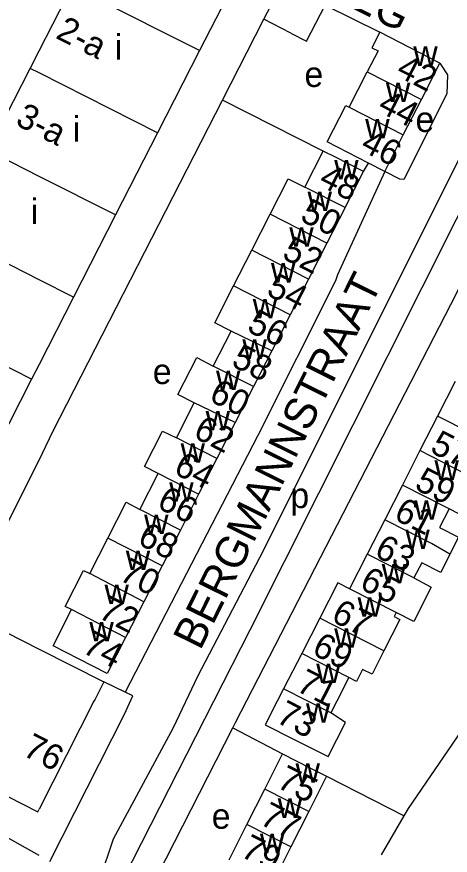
# Model space of a CAD drawing. Extents: x 159700 to 161346, y 381730 to 382922.
# Drawn here: x 160696.5 to 160765.1, y 382225.6 to 382358.4 of the extents above; entities that cross this region are included whole.
import ezdxf

# ---------------------------------------------------------------- set-up
doc = ezdxf.new("R2010")
doc.units = 0
for name, color, linetype in [('BLT_Basislijn', 7, 'Continuous'), ('BLT_Bebouwing', 7, 'Continuous'), ('BLT_Centroide', 7, 'Continuous'), ('BLT_Huisnummer', 7, 'Continuous'), ('BLT_Huisnummer_ tussenligend', 7, 'Continuous'), ('BLT_Huisnummer_reeks', 7, 'Continuous'), ('BLT_Onderverdeling_panden', 7, 'Continuous'), ('BLT_Straatnaam', 7, 'Continuous')]:
    doc.layers.add(name, color=color, linetype=linetype)

msp = doc.modelspace()

# ---------------------------------------------------------------- linework, layer by layer
at = {"layer": 'BLT_Basislijn'}
for p, q in [((160745.3, 382360.23), (160753.96, 382355.93)), ((160729.04, 382345.2), (160735.6, 382358)), ((160745.01, 382337.11), (160729.04, 382345.2)), ((160751.38, 382333.88), (160752.15, 382335.23)), ((160713.63, 382251.43), (160710.25, 382253.07)), ((160715.82, 382216.7), (160730.71, 382245.8)), ((160730.71, 382245.8), (160738.54, 382241.65)), ((160745.51, 382238.13), (160757.83, 382231.86)), ((160754.21, 382225.67), (160757.83, 382231.86))]:
    msp.add_line(p, q, dxfattribs=at)
for points in [[(160711.94, 382219.12), (160709.81, 382221.08), (160709.6, 382221.78), (160711.76, 382228.19), (160721.29, 382245.86), (160725.12, 382253.95), (160734.96, 382272.74), (160773.93, 382350.62)], [(160711.94, 382219.12), (160733.42, 382261.33), (160777.01, 382347.97), (160777.1, 382348.8), (160773.93, 382350.62)], [(160763.5, 382351.06), (160764.68, 382349.21), (160764.58, 382346.18), (160757.76, 382332.63), (160757.14, 382332.69), (160754.74, 382333.91)], [(160700, 382288.17), (160702.15, 382292.71), (160729.04, 382345.2)], [(160730.71, 382245.8), (160731.13, 382246.62), (160765.23, 382312.81), (160779.87, 382341.97), (160781.08, 382341.34)], [(160754.74, 382333.91), (160747.25, 382317.55), (160746.93, 382316.59), (160734.65, 382292.08), (160713.63, 382251.43)], [(160689.26, 382263.71), (160688.64, 382265.69), (160700, 382288.17)], [(160757.83, 382231.86), (160758.51, 382233.03), (160777.45, 382260.73)], [(160701.68, 382224.62), (160713.51, 382247.93), (160714.82, 382250.85), (160713.63, 382251.43)], [(160700, 382225.56), (160680.12, 382236.72), (160678.04, 382235.69)]]:
    msp.add_lwpolyline(points, dxfattribs=at)
at = {"layer": 'BLT_Bebouwing'}
for p, q in [((160700, 382353.02), (160705.22, 382363.22)), ((160735.6, 382358), (160738.15, 382362.99)), ((160739.85, 382355.82), (160735.6, 382358)), ((160763.5, 382351.06), (160753.96, 382355.93)), ((160698.57, 382350.22), (160700, 382353.02)), ((160725.42, 382353.03), (160718.77, 382340.02)), ((160760.55, 382345.3), (160763.5, 382351.06)), ((160691.91, 382337.21), (160698.57, 382350.22)), ((160757.69, 382339.7), (160760.55, 382345.3)), ((160718.77, 382340.02), (160712.12, 382327.01)), ((160754.74, 382333.91), (160757.69, 382339.7)), ((160742.09, 382331.39), (160745.01, 382337.11)), ((160748.48, 382328.21), (160745.58, 382322.53)), ((160712.12, 382327.01), (160705.46, 382314)), ((160733.69, 382321.44), (160736.59, 382327.12)), ((160730.79, 382315.76), (160733.69, 382321.44)), ((160745.58, 382322.53), (160742.68, 382316.85)), ((160742.68, 382316.85), (160739.78, 382311.17)), ((160705.46, 382314), (160700, 382303.31)), ((160739.78, 382311.17), (160736.88, 382305.49)), ((160727.58, 382303.08), (160730.41, 382308.62)), ((160736.88, 382305.49), (160733.97, 382299.82)), ((160700, 382303.31), (160698.81, 382300.99)), ((160698.81, 382300.99), (160692.16, 382287.98)), ((160765.88, 382300.63), (160763.1, 382295.16)), ((160733.97, 382299.82), (160731.07, 382294.14)), ((160721.75, 382291.74), (160724.58, 382297.28)), ((160763.1, 382295.16), (160760.32, 382289.69)), ((160731.07, 382294.14), (160728.17, 382288.46)), ((160760.32, 382289.69), (160757.54, 382284.22)), ((160728.17, 382288.46), (160725.27, 382282.78)), ((160715.95, 382280.38), (160718.85, 382286.06)), ((160757.54, 382284.22), (160754.75, 382278.75)), ((160725.27, 382282.78), (160722.37, 382277.1)), ((160754.75, 382278.75), (160751.97, 382273.28)), ((160722.37, 382277.1), (160719.47, 382271.43)), ((160751.97, 382273.28), (160749.19, 382267.81)), ((160719.47, 382271.43), (160716.57, 382265.75)), ((160716.57, 382265.75), (160713.67, 382260.07)), ((160744.45, 382263.17), (160741.59, 382257.58)), ((160700, 382258.27), (160710.25, 382253.07)), ((160741.59, 382257.58), (160738.73, 382251.99)), ((160735.73, 382236.07), (160738.54, 382241.65)), ((160745.51, 382238.13), (160742.7, 382232.55)), ((160732.91, 382230.48), (160735.73, 382236.07)), ((160742.7, 382232.55), (160739.88, 382226.97)), ((160730.09, 382224.9), (160732.91, 382230.48)), ((160739.88, 382226.97), (160737.06, 382221.38))]:
    msp.add_line(p, q, dxfattribs=at)
for points in [[(160731.53, 382366.3), (160731.79, 382365.49), (160729.74, 382361.48), (160725.42, 382353.03)], [(160739.85, 382355.82), (160742.37, 382354.51), (160745.3, 382360.23)], [(160753.96, 382355.93), (160752.72, 382353.5), (160753.68, 382353.01), (160751.98, 382349.68)], [(160749.12, 382344.08), (160751.98, 382349.68)], [(160752.15, 382335.23), (160745.61, 382338.57), (160748.57, 382344.36), (160749.12, 382344.08)], [(160751.38, 382333.88), (160746.93, 382336.16), (160745.01, 382337.11)], [(160754.74, 382333.91), (160752.15, 382335.23)], [(160748.48, 382328.21), (160751.38, 382333.88)], [(160736.59, 382327.12), (160739.46, 382332.74), (160742.09, 382331.39)], [(160730.41, 382308.62), (160727.82, 382309.95), (160730.79, 382315.76)], [(160724.58, 382297.28), (160721.98, 382298.6), (160724.97, 382304.45), (160727.58, 382303.08)], [(160718.85, 382286.06), (160716.7, 382287.18), (160719.56, 382292.79), (160721.75, 382291.74)], [(160767.71, 382285.93), (160767.49, 382285.49), (160770.47, 382283.98), (160767.9, 382278.94), (160764.93, 382280.46)], [(160710.89, 382275.81), (160713.8, 382281.52), (160715.95, 382280.38)], [(160764.93, 382280.46), (160763.42, 382277.49), (160766.43, 382275.96), (160765.07, 382273.28)], [(160708.03, 382270.22), (160710.89, 382275.81)], [(160765.07, 382273.28), (160763.61, 382270.41), (160760.6, 382271.94), (160759.36, 382269.52)], [(160705.15, 382264.52), (160704.14, 382265.03), (160707.02, 382270.73), (160708.03, 382270.22)], [(160759.36, 382269.52), (160762.11, 382268.08), (160759.34, 382262.64), (160756.57, 382264.04)], [(160749.19, 382267.81), (160747.32, 382268.76), (160744.45, 382263.17)], [(160713.67, 382260.07), (160710.77, 382254.39), (160706.32, 382256.67), (160702.21, 382258.76), (160705.15, 382264.52)], [(160756.57, 382264.04), (160756.25, 382263.4), (160757.14, 382262.95), (160754.62, 382257.97)], [(160691.96, 382262.33), (160700, 382258.27)], [(160754.62, 382257.97), (160752.75, 382254.27), (160751.22, 382255.04), (160750.26, 382253.15), (160749.06, 382253.76)], [(160749.06, 382253.76), (160747.16, 382250), (160746.23, 382248.16)], [(160710.25, 382253.07), (160708.92, 382250.46), (160708.86, 382250.34), (160708.69, 382250), (160700, 382232.89)], [(160738.73, 382251.99), (160737.71, 382250), (160735.82, 382246.26), (160740.28, 382244), (160745.81, 382241.27), (160748.54, 382246.66), (160746.23, 382248.16)], [(160678.36, 382243.83), (160683.26, 382241.34), (160683.09, 382240.99), (160699.8, 382232.5), (160700, 382232.89)], [(160738.54, 382241.65), (160743.01, 382239.4), (160745.51, 382238.13)]]:
    msp.add_lwpolyline(points, dxfattribs=at)
at = {"layer": 'BLT_Onderverdeling_panden'}
for p, q in [((160725.42, 382353.03), (160705.22, 382363.22)), ((160700, 382349.49), (160698.57, 382350.22)), ((160718.77, 382340.02), (160700, 382349.49)), ((160749.12, 382344.08), (160757.69, 382339.7)), ((160700, 382333.12), (160691.91, 382337.21)), ((160712.12, 382327.01), (160700, 382333.12)), ((160748.48, 382328.21), (160742.09, 382331.39)), ((160745.58, 382322.53), (160736.59, 382327.12)), ((160700, 382316.76), (160685.26, 382324.2)), ((160742.68, 382316.85), (160733.69, 382321.44)), ((160705.46, 382314), (160700, 382316.76)), ((160739.78, 382311.17), (160730.79, 382315.76)), ((160698.81, 382300.99), (160678.61, 382311.19)), ((160736.88, 382305.49), (160730.41, 382308.62)), ((160733.97, 382299.82), (160727.58, 382303.08)), ((160731.07, 382294.14), (160724.58, 382297.28)), ((160770.49, 382291.4), (160763.1, 382295.16)), ((160728.17, 382288.46), (160721.75, 382291.74)), ((160767.71, 382285.93), (160760.32, 382289.69)), ((160725.27, 382282.78), (160718.85, 382286.06)), ((160764.93, 382280.46), (160757.54, 382284.22)), ((160722.37, 382277.1), (160715.95, 382280.38)), ((160719.47, 382271.43), (160710.89, 382275.81)), ((160759.36, 382269.52), (160751.97, 382273.28)), ((160716.57, 382265.75), (160708.03, 382270.22)), ((160756.57, 382264.04), (160749.19, 382267.81)), ((160713.67, 382260.07), (160705.15, 382264.52)), ((160754.62, 382257.97), (160744.45, 382263.17)), ((160749.06, 382253.76), (160741.59, 382257.58)), ((160746.23, 382248.16), (160738.73, 382251.99)), ((160742.7, 382232.55), (160735.73, 382236.07)), ((160739.88, 382226.97), (160732.91, 382230.48))]:
    msp.add_line(p, q, dxfattribs=at)
for points in [[(160751.98, 382349.68), (160760.55, 382345.3)], [(160765.07, 382273.28), (160762.14, 382274.99), (160754.75, 382278.75)]]:
    msp.add_lwpolyline(points, dxfattribs=at)

# ---------------------------------------------------------------- texts
at = {"layer": 'BLT_Centroide'}
for s, p in [('i', (160711.99, 382351.62)), ('w', (160759.27, 382350.62)), ('e', (160742.03, 382347.28)), ('w', (160754.93, 382344.88)), ('i', (160705.34, 382338.62)), ('e', (160759.62, 382340.15)), ('w', (160751.65, 382339.12)), ('w', (160746.74, 382332.66)), ('w', (160742.52, 382327.62)), ('i', (160698.69, 382325.59)), ('w', (160739.63, 382322)), ('w', (160736.73, 382316.31)), ('w', (160733.84, 382310.62)), ('w', (160732.2, 382304.22)), ('e', (160718.01, 382300.23)), ('w', (160728.02, 382299.28)), ('w', (160726.38, 382292.88)), ('w', (160722.41, 382287.78)), ('w', (160762.62, 382285.06)), ('w', (160720.61, 382281.59)), ('p', (160739.8, 382280.6)), ('w', (160759.41, 382278.75)), ('w', (160716.63, 382276.47)), ('w', (160758.01, 382274.12)), ('w', (160713.73, 382270.78)), ('w', (160754.27, 382268.66)), ('w', (160710.36, 382265.41)), ('w', (160750.44, 382263.38)), ('w', (160707.96, 382259.47)), ('w', (160746.74, 382258.47)), ('w', (160743.89, 382252.88)), ('w', (160742.26, 382246.62)), ('w', (160740.62, 382237.09)), ('w', (160737.8, 382231.53)), ('e', (160727.34, 382229.81)), ('w', (160734.98, 382225.94))]:
    msp.add_text(s, height=4, dxfattribs=at).set_placement(p)
at = {"layer": 'BLT_Huisnummer'}
for s, rotation, p in [('42', 332.941, (160756.36, 382349.13)), ('46', 332.9429, (160750.72, 382337.31)), ('50', 332.9399, (160741.15, 382326.21)), ('54', 332.9399, (160735.81, 382314.44)), ('58', 332.9352, (160730.26, 382303.2)), ('62', 332.9408, (160724.23, 382291.89)), ('57', 333.0364, (160761.74, 382289.53)), ('66', 332.9408, (160718.47, 382280.73)), ('61', 333.0333, (160756, 382278.9)), ('70', 332.9372, (160712.49, 382269.3)), ('65', 333.201, (160750.57, 382267.94)), ('74', 332.9404, (160706.63, 382257.81)), ('69', 333.1938, (160743.02, 382257.54)), ('73', 332.525, (160737.33, 382246.79)), ('76', 333.0755, (160697.22, 382241.53)), ('75', 333.2281, (160737.44, 382236.47)), ('79', 333.2281, (160731.72, 382225.53))]:
    msp.add_text(s, height=4, rotation=rotation, dxfattribs=at).set_placement(p)
at = {"layer": 'BLT_Huisnummer_ tussenligend'}
for s, rotation, p in [('44', 332.941, (160753.44, 382343.5)), ('48', 332.9429, (160744.11, 382331.79)), ('52', 332.9399, (160738.29, 382320.24)), ('56', 332.9399, (160732.72, 382308.7)), ('60', 332.9352, (160726.72, 382297.68)), ('64', 332.9408, (160721.12, 382286.15)), ('59', 333.0364, (160759.28, 382283.7)), ('68', 332.9408, (160715.39, 382274.99)), ('63', 333.0333, (160752.91, 382273.06)), ('72', 332.9372, (160709.18, 382263.33)), ('67', 333.201, (160746.08, 382262.79)), ('71', 333.1938, (160740.52, 382251.74)), ('77', 333.2281, (160734.74, 382230.65))]:
    msp.add_text(s, height=4, rotation=rotation, dxfattribs=at).set_placement(p)
at = {"layer": 'BLT_Huisnummer_reeks'}
for s, rotation, p in [('2-a', 333.213, (160702.46, 382355.09)), ('3-a', 333.212, (160696.06, 382341.37))]:
    msp.add_text(s, height=4, rotation=rotation, dxfattribs=at).set_placement(p)
at = {"layer": 'BLT_Straatnaam'}
for s, rotation, p in [('HALLENWEG', 333.4315, (160719.73, 382374.66)), ('BERGMANNSTRAAT', 63.6169, (160725.51, 382257.91))]:
    msp.add_text(s, height=5, rotation=rotation, dxfattribs=at).set_placement(p)

doc.saveas('drawing.dxf')
